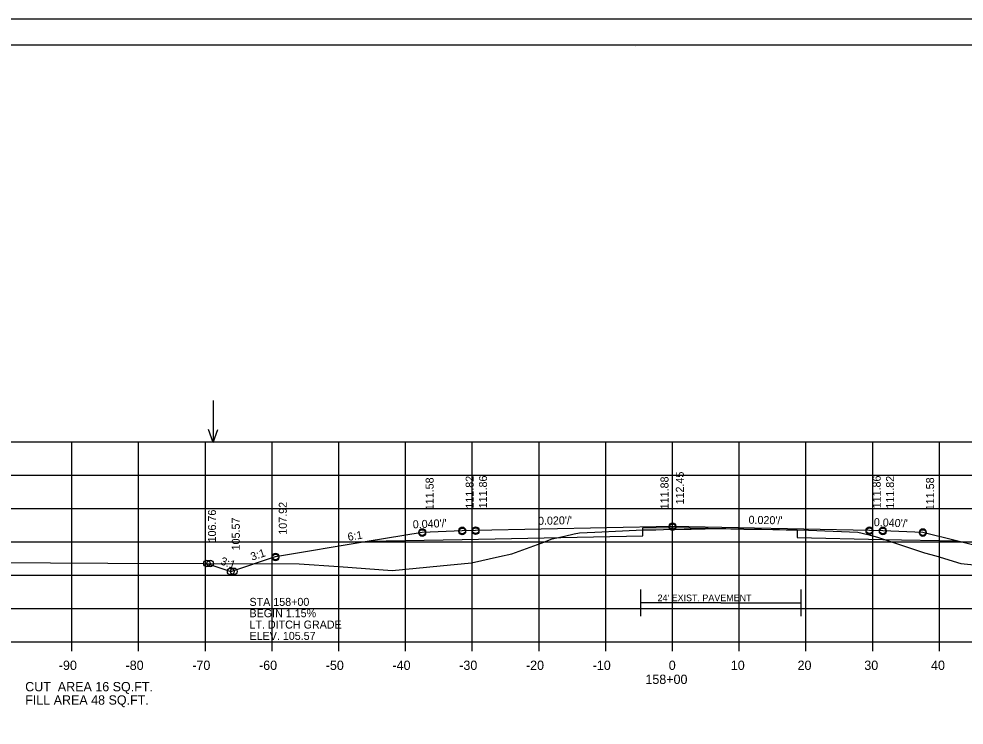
# Model space of a CAD drawing. Extents: x 1175611 to 1176402, y -433344 to -416213.
# Drawn here: x 1175683 to 1175824.7, y -428542.6 to -428436.8 of the extents above; entities that cross this region are included whole.
import ezdxf

# ---------------------------------------------------------------- set-up
doc = ezdxf.new("R2010")
doc.units = 0
for name, color, linetype in [('Default', 7, 'Continuous'), ('R_Alt Surface', 7, 'Continuous'), ('R_Axis', 7, 'Continuous'), ('R_Axis Annot', 7, 'Continuous'), ('R_Border', 7, 'Continuous'), ('R_Exist Surface', 7, 'Continuous'), ('R_Fin Surface', 7, 'Continuous'), ('R_Grid', 7, 'Continuous'), ('R_No Plot', 7, 'Continuous'), ('R_Water Annot', 7, 'Continuous'), ('R_Xsect Elev', 7, 'Continuous'), ('R_Xsect Slope', 7, 'Continuous')]:
    doc.layers.add(name, color=color, linetype=linetype)

msp = doc.modelspace()

# ---------------------------------------------------------------- linework, layer by layer
at = {"layer": 'R_Alt Surface'}
for q in [(1175776.22, -428524.24), (1175800.23, -428524.24)]:
    msp.add_line((1175788.22, -428524.24), q, dxfattribs=at)
for points in [[(1175735.2, -428515.02), (1175749.47, -428514.74), (1175776.5, -428514.19), (1175776.5, -428513.03), (1175780.97, -428512.94), (1175799.64, -428513.31), (1175799.65, -428514.48), (1175812.47, -428514.74), (1175823.75, -428514.96)], [(1175776.22, -428526.24), (1175776.22, -428522.24)], [(1175800.23, -428526.24), (1175800.23, -428522.24)]]:
    msp.add_lwpolyline(points, dxfattribs=at)
at = {"layer": 'R_Axis'}
for p, q in [((1175640.97, -428530.11), (1175920.97, -428530.11)), ((1175690.97, -428531.51), (1175690.97, -428530.11)), ((1175700.97, -428531.51), (1175700.97, -428530.11)), ((1175710.97, -428531.51), (1175710.97, -428530.11)), ((1175720.97, -428531.51), (1175720.97, -428530.11)), ((1175730.97, -428531.51), (1175730.97, -428530.11)), ((1175740.97, -428531.51), (1175740.97, -428530.11)), ((1175750.97, -428531.51), (1175750.97, -428530.11)), ((1175760.97, -428531.51), (1175760.97, -428530.11)), ((1175770.97, -428531.51), (1175770.97, -428530.11)), ((1175780.97, -428531.51), (1175780.97, -428530.11)), ((1175790.97, -428531.51), (1175790.97, -428530.11)), ((1175800.97, -428531.51), (1175800.97, -428530.11)), ((1175810.97, -428531.51), (1175810.97, -428530.11)), ((1175820.97, -428531.51), (1175820.97, -428530.11))]:
    msp.add_line(p, q, dxfattribs=at)
at = {"layer": 'R_Border'}
for p, q in [((1175622.97, -428440.65), (1175939.15, -428440.65)), ((1175775.49, -428440.91), (1175775.49, -428440.91)), ((1175775.49, -428440.91), (1175775.49, -428440.91))]:
    msp.add_line(p, q, dxfattribs=at)
at = {"layer": 'R_Exist Surface'}
msp.add_lwpolyline([(1175679.1, -428518.21), (1175696.34, -428518.3), (1175725.01, -428518.41), (1175730.97, -428518.82), (1175738.94, -428519.4), (1175746.16, -428518.71), (1175750.85, -428518.26), (1175755.02, -428517.31), (1175756.91, -428516.9), (1175761.28, -428515.29), (1175762.94, -428514.66), (1175764.76, -428514.25), (1175766.21, -428513.92), (1175767.01, -428513.74), (1175769.35, -428513.64), (1175773.49, -428513.45), (1175776.5, -428513.3), (1175776.51, -428513.3), (1175776.77, -428513.31), (1175778.18, -428513.32), (1175778.47, -428513.31), (1175779.62, -428513.26), (1175782.73, -428513.21), (1175783.78, -428513.19), (1175785.58, -428513.15), (1175785.84, -428513.14), (1175786.82, -428513.1), (1175787.97, -428513.12), (1175788.22, -428513.13), (1175789.69, -428513.15), (1175790.02, -428513.16), (1175791.65, -428513.19), (1175792.06, -428513.2), (1175793.2, -428513.2), (1175793.94, -428513.21), (1175798.01, -428513.29), (1175798.65, -428513.31), (1175799.64, -428513.32), (1175801.35, -428513.38), (1175805.06, -428513.52), (1175808.76, -428513.67), (1175810.23, -428514.03), (1175811.68, -428514.41), (1175816.03, -428515.86), (1175818.71, -428516.75), (1175820.43, -428517.23), (1175824.2, -428518.37), (1175832.16, -428519.16)], dxfattribs=at)
at = {"layer": 'R_Fin Surface'}
msp.add_lwpolyline([(1175711.2, -428518.36), (1175714.76, -428519.54), (1175721.47, -428517.31), (1175735.2, -428515.02), (1175743.47, -428513.64), (1175749.47, -428513.4), (1175751.47, -428513.36), (1175780.97, -428512.77), (1175810.47, -428513.36), (1175812.47, -428513.4), (1175818.47, -428513.64), (1175823.75, -428514.96), (1175840.47, -428519.14), (1175841.62, -428519.52), (1175843.21, -428518.99)], dxfattribs=at)
at = {"layer": 'R_Grid'}
for p, q in [((1175640.97, -428500.11), (1175920.97, -428500.11)), ((1175690.97, -428530.11), (1175690.97, -428500.11)), ((1175700.97, -428530.11), (1175700.97, -428500.11)), ((1175710.97, -428530.11), (1175710.97, -428500.11)), ((1175720.97, -428530.11), (1175720.97, -428500.11)), ((1175730.97, -428530.11), (1175730.97, -428500.11)), ((1175740.97, -428530.11), (1175740.97, -428500.11)), ((1175750.97, -428530.11), (1175750.97, -428500.11)), ((1175760.97, -428530.11), (1175760.97, -428500.11)), ((1175770.97, -428530.11), (1175770.97, -428500.11)), ((1175780.97, -428530.11), (1175780.97, -428500.11)), ((1175790.97, -428530.11), (1175790.97, -428500.11)), ((1175800.97, -428530.11), (1175800.97, -428500.11)), ((1175810.97, -428530.11), (1175810.97, -428500.11)), ((1175820.97, -428530.11), (1175820.97, -428500.11)), ((1175640.97, -428505.11), (1175920.97, -428505.11)), ((1175640.97, -428510.11), (1175920.97, -428510.11)), ((1175640.97, -428515.11), (1175920.97, -428515.11)), ((1175640.97, -428520.11), (1175920.97, -428520.11)), ((1175640.97, -428525.11), (1175920.97, -428525.11)), ((1175640.97, -428530.11), (1175920.97, -428530.11))]:
    msp.add_line(p, q, dxfattribs=at)
at = {"layer": 'R_No Plot'}
msp.add_line((1175610.57, -428436.76), (1175943.91, -428436.76), dxfattribs=at)
msp.add_lwpolyline([(1175610.57, -428436.76), (1175943.91, -428436.76), (1175943.91, -428650.1), (1175610.57, -428650.1)], close=True, dxfattribs=at)
for centre in [(1175780.97, -428512.77), (1175743.47, -428513.64), (1175743.47, -428513.79), (1175749.47, -428513.4), (1175749.47, -428513.55), (1175751.47, -428513.36), (1175751.47, -428513.51), (1175780.97, -428512.92), (1175810.47, -428513.36), (1175810.47, -428513.51), (1175812.47, -428513.4), (1175812.47, -428513.55), (1175818.47, -428513.64), (1175818.47, -428513.79), (1175711.2, -428518.36), (1175711.2, -428518.36), (1175711.68, -428518.36), (1175721.47, -428517.31), (1175721.47, -428517.46), (1175714.76, -428519.54), (1175715.23, -428519.54)]:
    msp.add_circle(centre, 0.5, dxfattribs=at)
at = {"layer": 'R_Water Annot'}
for p, q in [((1175712.16, -428493.94), (1175712.16, -428500.22)), ((1175712.16, -428500.22), (1175711.46, -428498.3)), ((1175712.16, -428500.22), (1175712.86, -428498.3))]:
    msp.add_line(p, q, dxfattribs=at)

# ---------------------------------------------------------------- texts
at = {"layer": 'Default'}
for s, p in [('CUT  AREA 16 SQ.FT.', (1175683.97, -428537.51)), ('FILL AREA 48 SQ.FT.', (1175683.97, -428539.51))]:
    msp.add_text(s, height=1.4, dxfattribs=at).set_placement(p)
at = {"layer": 'R_Alt Surface'}
msp.add_text("24' EXIST. PAVEMENT", height=1, dxfattribs=at).set_placement((1175778.73, -428524.01))
at = {"layer": 'R_Axis Annot'}
for s, p in [('-90', (1175689.01, -428534.31)), ('-80', (1175699.01, -428534.31)), ('-70', (1175709.01, -428534.31)), ('-60', (1175719.01, -428534.31)), ('-50', (1175729.01, -428534.31)), ('-40', (1175739.01, -428534.31)), ('-30', (1175749.01, -428534.31)), ('-20', (1175759.01, -428534.31)), ('-10', (1175769.01, -428534.31)), ('0', (1175780.41, -428534.31)), ('10', (1175789.71, -428534.31)), ('20', (1175799.71, -428534.31)), ('30', (1175809.71, -428534.31)), ('40', (1175819.71, -428534.31)), ('158+00', (1175776.91, -428536.41))]:
    msp.add_text(s, height=1.4, dxfattribs=at).set_placement(p)
at = {"layer": 'R_Water Annot'}
for s, p in [('STA 158+00', (1175717.58, -428524.71)), ('BEGIN 1.15%', (1175717.58, -428526.41)), ('LT. DITCH GRADE', (1175717.58, -428528.11)), ('ELEV. 105.57', (1175717.58, -428529.81))]:
    msp.add_text(s, height=1.2, dxfattribs=at).set_placement(p)
at = {"layer": 'R_Xsect Elev'}
for s, p in [('111.82', (1175751.17, -428510.13)), ('111.86', (1175753.17, -428510.09)), ('112.45', (1175782.67, -428509.5)), ('111.86', (1175812.17, -428510.09)), ('111.82', (1175814.17, -428510.13)), ('111.58', (1175745.17, -428510.37)), ('111.88', (1175780.37, -428510.23)), ('111.58', (1175820.17, -428510.37)), ('107.92', (1175723.17, -428514.04)), ('106.76', (1175712.56, -428515.2)), ('105.57', (1175716.13, -428516.39))]:
    msp.add_text(s, height=1.2, rotation=90, dxfattribs=at).set_placement(p)
at = {"layer": 'R_Xsect Slope'}
for s, rotation, p in [("0.040'/'", 2.2906, (1175742.07, -428513.1)), ("0.020'/'", 1.1458, (1175760.83, -428512.57)), ("0.020'/'", 358.8542, (1175792.36, -428512.4)), ("0.040'/'", 357.7094, (1175811.12, -428512.75)), ('6:1', 9.4623, (1175732.39, -428514.98)), ('3:1', 18.4349, (1175717.96, -428517.95)), ('3:1', 341.5651, (1175713.14, -428518.48))]:
    msp.add_text(s, height=1.2, rotation=rotation, dxfattribs=at).set_placement(p)

doc.saveas('drawing.dxf')
